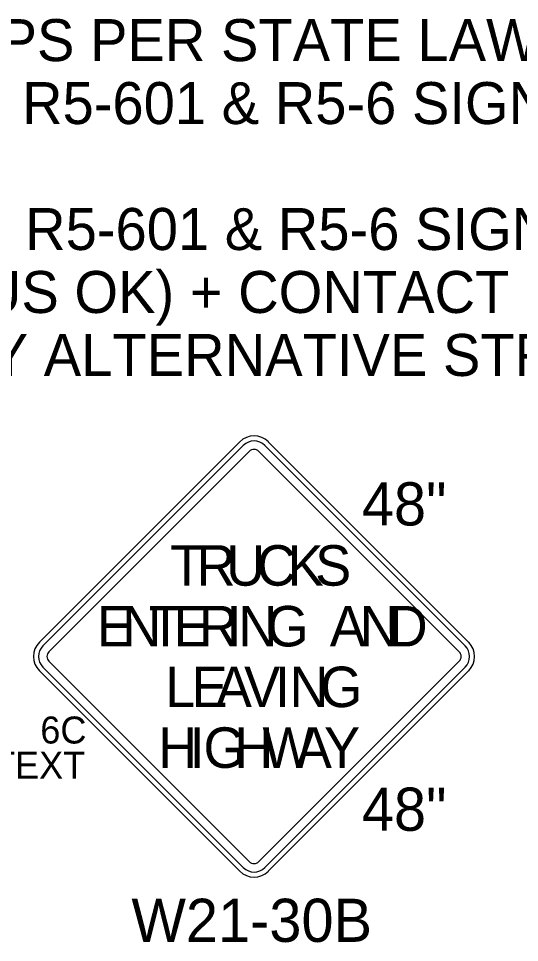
# Model space of a CAD drawing. Extents: x 99999 to 100116, y 99995 to 100013.
# Drawn here: x 100033.098 to 100033.934, y 100001.176 to 100002.717 of the extents above; entities that cross this region are included whole.
import ezdxf

# ---------------------------------------------------------------- set-up
doc = ezdxf.new("R2010")
doc.units = 0
doc.layers.add('SH_GI_GeneralNotesBodyText', color=7, linetype='Continuous')
doc.layers.add('TR_SN_ConstructionSigns', color=7, linetype='Continuous')

msp = doc.modelspace()

# ---------------------------------------------------------------- linework, layer by layer
at = {"layer": 'TR_SN_ConstructionSigns'}
for p, q in [((100033.4669, 100002.0107), (100033.1328, 100001.6766)), ((100033.4729, 100002.0048), (100033.1387, 100001.6707)), ((100033.8428, 100001.6707), (100033.5087, 100002.0048)), ((100033.8487, 100001.6766), (100033.5146, 100002.0107)), ((100033.1487, 100001.6607), (100033.4828, 100001.9948)), ((100033.4987, 100001.9948), (100033.8328, 100001.6607)), ((100033.4828, 100001.3107), (100033.1487, 100001.6448)), ((100033.8328, 100001.6448), (100033.4987, 100001.3107)), ((100033.1328, 100001.6289), (100033.4669, 100001.2948)), ((100033.1387, 100001.6349), (100033.4729, 100001.3008)), ((100033.5087, 100001.3008), (100033.8428, 100001.6349)), ((100033.5146, 100001.2948), (100033.8487, 100001.6289))]:
    msp.add_line(p, q, dxfattribs=at)
for centre, radius, start, end in [((100033.4908, 100001.9869), 0.0338, 45, 135), ((100033.4908, 100001.9869), 0.0253, 45, 135), ((100033.4908, 100001.9869), 0.0113, 45, 135), ((100033.1566, 100001.6528), 0.0338, 135, 225), ((100033.8249, 100001.6528), 0.0338, 315, 45), ((100033.1566, 100001.6528), 0.0253, 135, 225), ((100033.1566, 100001.6528), 0.0113, 135, 225), ((100033.8249, 100001.6528), 0.0113, 315, 45), ((100033.8249, 100001.6528), 0.0253, 315, 45), ((100033.4908, 100001.3187), 0.0113, 225, 315), ((100033.4908, 100001.3187), 0.0338, 225, 315), ((100033.4908, 100001.3187), 0.0253, 225, 315)]:
    msp.add_arc(centre, radius, start, end, dxfattribs=at)

# ---------------------------------------------------------------- texts
at = {"layer": 'SH_GI_GeneralNotesBodyText'}
for s, p in [('EXIT-RAMPS, AND ON-RAMPS PER STATE LAW.', (100031.839, 100002.6456)), ('(B) BICYCLES PROHIBITED VIA R5-601 & R5-6 SIGNS. PROVIDE SIGNED DETOUR ', (100031.689, 100002.5406)), ('(C) BICYCLES PROHIBITED VIA R5-601 & R5-6 SIGNS. PROVIDE FREE SHUTTLE ', (100031.689, 100002.3306)), ('(WORK TRUCK, VAN, OR BUS OK) + CONTACT INFORMATION OR PHONE BOX.', (100031.839, 100002.2256)), ('(D) ENGINEER TO ACCEPT ANY ALTERNATIVE STRATEGIES.', (100031.689, 100002.1206))]:
    msp.add_text(s, height=0.07, rotation=360, dxfattribs=at).set_placement(p)
at = {"layer": 'TR_SN_ConstructionSigns'}
for s, p in [('48"', (100033.6706, 100001.8713)), ('48"', (100033.6706, 100001.3622)), ('W21-30B', (100033.2863, 100001.1769))]:
    msp.add_text(s, height=0.072, rotation=360, dxfattribs=at).set_placement(p)
for s, height, p in [('T', 0.0675, (100033.351, 100001.7709)), ('R', 0.0675, (100033.3949, 100001.7709)), ('U', 0.0675, (100033.4442, 100001.7709)), ('C', 0.0675, (100033.4955, 100001.7709)), ('K', 0.0675, (100033.5468, 100001.7709)), ('S', 0.0675, (100033.5927, 100001.7709)), ('E', 0.0675, (100033.2286, 100001.6696)), ('N', 0.0675, (100033.271, 100001.6696)), ('T', 0.0675, (100033.3154, 100001.6696)), ('E', 0.0675, (100033.3565, 100001.6696)), ('R', 0.0675, (100033.3989, 100001.6696)), ('I', 0.0675, (100033.4448, 100001.6696)), ('N', 0.0675, (100033.4646, 100001.6696)), ('G', 0.0675, (100033.5118, 100001.6696)), ('A', 0.0675, (100033.6171, 100001.6696)), ('N', 0.0675, (100033.667, 100001.6696)), ('D', 0.0675, (100033.7152, 100001.6696)), ('L', 0.0675, (100033.3426, 100001.5684)), ('E', 0.0675, (100033.3865, 100001.5684)), ('A', 0.0675, (100033.427, 100001.5684)), ('V', 0.0675, (100033.4742, 100001.5684)), ('I', 0.0675, (100033.5255, 100001.5684)), ('N', 0.0675, (100033.5498, 100001.5684)), ('G', 0.0675, (100033.6011, 100001.5684)), ('6C', 0.045, (100033.1343, 100001.5077)), ('H', 0.0675, (100033.3308, 100001.4671)), ('I', 0.0675, (100033.3834, 100001.4671)), ('G', 0.0675, (100033.4064, 100001.4671)), ('H', 0.0675, (100033.4577, 100001.4671)), ('W', 0.0675, (100033.5049, 100001.4671)), ('A', 0.0675, (100033.5603, 100001.4671)), ('Y', 0.0675, (100033.6075, 100001.4671)), ('TEXT', 0.045, (100033.0554, 100001.4491))]:
    msp.add_text(s, height=height, dxfattribs=at).set_placement(p)

doc.saveas('drawing.dxf')
